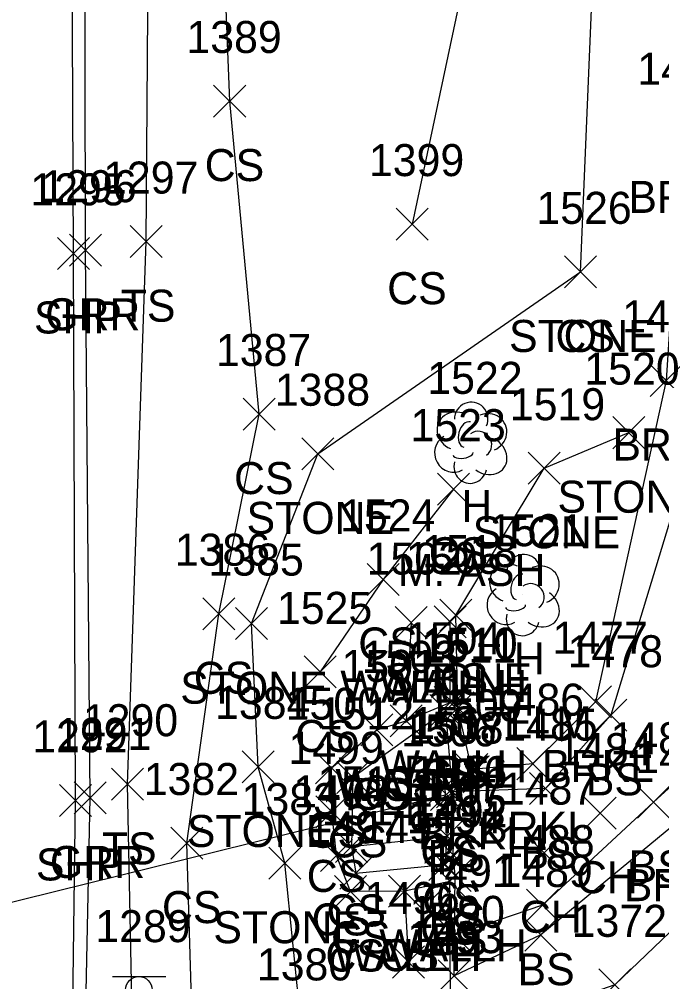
# Model space of a CAD drawing. Extents: x 1618262 to 1622220, y 273782 to 283685.
# Drawn here: x 1622080.2 to 1622120.3, y 282698.6 to 282758.7 of the extents above; entities that cross this region are included whole.
import ezdxf

# ---------------------------------------------------------------- set-up
doc = ezdxf.new("R2010")
doc.units = 0
for name, color, linetype in [('D_A', 7, 'Continuous'), ('D_I', 7, 'Continuous'), ('D_TIC', 7, 'Continuous'), ('DCP', 7, 'Continuous'), ('DHW', 7, 'Continuous'), ('L_A', 7, 'Continuous'), ('L_C', 7, 'Continuous'), ('L_I', 7, 'Continuous'), ('L_TIC', 7, 'Continuous'), ('LASF', 7, 'Continuous'), ('LAWE', 7, 'Continuous'), ('LELB', 7, 'Continuous'), ('LTD', 7, 'Continuous'), ('P_A', 7, 'Continuous'), ('P_I', 7, 'Continuous'), ('P_TIC', 7, 'Continuous'), ('PSP', 7, 'Continuous'), ('R_A', 7, 'Continuous'), ('R_I', 7, 'Continuous'), ('R_TIC', 7, 'Continuous'), ('RGR', 7, 'Continuous'), ('S_I', 7, 'Continuous'), ('SSGN', 7, 'Continuous')]:
    doc.layers.add(name, color=color, linetype=linetype)

msp = doc.modelspace()

# ---------------------------------------------------------------- linework, layer by layer
at = {"layer": 'D_TIC'}
for points in [[(1622106.144, 282720.106), (1622108.144, 282722.106)], [(1622108.144, 282720.106), (1622106.144, 282722.106)], [(1622103.693, 282720.06), (1622105.693, 282722.06)], [(1622105.693, 282720.06), (1622103.693, 282722.06)], [(1622106.143, 282715.082), (1622108.143, 282717.082)], [(1622108.143, 282715.082), (1622106.143, 282717.082)], [(1622103.384, 282713.927), (1622105.384, 282715.927)], [(1622105.384, 282713.927), (1622103.384, 282715.927)], [(1622105.908, 282709.335), (1622107.908, 282711.335)], [(1622107.908, 282709.335), (1622105.908, 282711.335)], [(1622106.12, 282703.906), (1622108.12, 282705.906)], [(1622108.12, 282703.906), (1622106.12, 282705.906)], [(1622103.281, 282703.297), (1622105.281, 282705.297)], [(1622105.281, 282703.297), (1622103.281, 282705.297)], [(1622103.534, 282698.869), (1622105.534, 282700.869)], [(1622105.534, 282698.869), (1622103.534, 282700.869)]]:
    msp.add_lwpolyline(points, dxfattribs=at)
at = {"layer": 'DCP'}
msp.add_lwpolyline([(1622023.295, 282689.629), (1622106.908, 282710.335)], dxfattribs=at)
at = {"layer": 'DHW'}
for points in [[(1622104.693, 282721.06), (1622104.384, 282714.927), (1622107.143, 282716.082), (1622107.144, 282721.106)], [(1622107.156, 282697.422), (1622107.12, 282704.906), (1622104.281, 282704.297), (1622104.534, 282699.869)]]:
    msp.add_lwpolyline(points, dxfattribs=at)
at = {"layer": 'L_TIC'}
for points in [[(1622092.371, 282752.634), (1622094.371, 282754.634)], [(1622094.371, 282752.634), (1622092.371, 282754.634)], [(1622103.765, 282744.946), (1622105.765, 282746.946)], [(1622105.765, 282744.946), (1622103.765, 282746.946)], [(1622087.16, 282743.854), (1622089.16, 282745.854)], [(1622089.16, 282743.854), (1622087.16, 282745.854)], [(1622114.268, 282741.964), (1622116.268, 282743.964)], [(1622116.268, 282741.964), (1622114.268, 282743.964)], [(1622114.268, 282741.964), (1622116.268, 282743.964)], [(1622116.268, 282741.964), (1622114.268, 282743.964)], [(1622119.62, 282735.185), (1622121.62, 282737.185)], [(1622121.62, 282735.185), (1622119.62, 282737.185)], [(1622094.205, 282733.089), (1622096.205, 282735.089)], [(1622096.205, 282733.089), (1622094.205, 282735.089)], [(1622117.294, 282731.925), (1622119.294, 282733.925)], [(1622119.294, 282731.925), (1622117.294, 282733.925)], [(1622097.882, 282730.605), (1622099.882, 282732.605)], [(1622099.882, 282730.605), (1622097.882, 282732.605)], [(1622111.999, 282729.702), (1622113.999, 282731.702)], [(1622113.999, 282729.702), (1622111.999, 282731.702)], [(1622106.354, 282728.393), (1622108.354, 282730.393)], [(1622108.354, 282728.393), (1622106.354, 282730.393)], [(1622101.958, 282722.759), (1622103.958, 282724.759)], [(1622103.958, 282722.759), (1622101.958, 282724.759)], [(1622091.692, 282720.617), (1622093.692, 282722.617)], [(1622093.692, 282720.617), (1622091.692, 282722.617)], [(1622106.5, 282720.524), (1622108.5, 282722.524)], [(1622108.5, 282720.524), (1622106.5, 282722.524)], [(1622106.5, 282720.524), (1622108.5, 282722.524)], [(1622108.5, 282720.524), (1622106.5, 282722.524)], [(1622093.742, 282719.999), (1622095.742, 282721.999)], [(1622095.742, 282719.999), (1622093.742, 282721.999)], [(1622098.016, 282716.984), (1622100.016, 282718.984)], [(1622100.016, 282716.984), (1622098.016, 282718.984)], [(1622106.608, 282714.746), (1622108.608, 282716.746)], [(1622108.608, 282714.746), (1622106.608, 282716.746)], [(1622106.608, 282714.746), (1622108.608, 282716.746)], [(1622108.608, 282714.746), (1622106.608, 282716.746)], [(1622115.219, 282715.114), (1622117.219, 282717.114)], [(1622117.219, 282715.114), (1622115.219, 282717.114)], [(1622105.865, 282714.564), (1622107.865, 282716.564)], [(1622107.865, 282714.564), (1622105.865, 282716.564)], [(1622105.865, 282714.564), (1622107.865, 282716.564)], [(1622107.865, 282714.564), (1622105.865, 282716.564)], [(1622116.166, 282714.275), (1622118.166, 282716.275)], [(1622118.166, 282714.275), (1622116.166, 282716.275)], [(1622103.384, 282713.927), (1622105.384, 282715.927)], [(1622105.384, 282713.927), (1622103.384, 282715.927)], [(1622101.555, 282713.362), (1622103.555, 282715.362)], [(1622103.555, 282713.362), (1622101.555, 282715.362)], [(1622111.294, 282711.254), (1622113.294, 282713.254)], [(1622113.294, 282711.254), (1622111.294, 282713.254)], [(1622094.152, 282711.05), (1622096.152, 282713.05)], [(1622096.152, 282711.05), (1622094.152, 282713.05)], [(1622098.727, 282711.001), (1622100.727, 282713.001)], [(1622100.727, 282711.001), (1622098.727, 282713.001)], [(1622107.48, 282710.9), (1622109.48, 282712.9)], [(1622109.48, 282710.9), (1622107.48, 282712.9)], [(1622085.983, 282709.968), (1622087.983, 282711.968)], [(1622087.983, 282709.968), (1622085.983, 282711.968)], [(1622100.055, 282710.4), (1622102.055, 282712.4)], [(1622102.055, 282710.4), (1622100.055, 282712.4)], [(1622100.055, 282710.4), (1622102.055, 282712.4)], [(1622102.055, 282710.4), (1622100.055, 282712.4)], [(1622105.831, 282709.797), (1622107.831, 282711.797)], [(1622107.831, 282709.797), (1622105.831, 282711.797)], [(1622105.831, 282709.797), (1622107.831, 282711.797)], [(1622107.831, 282709.797), (1622105.831, 282711.797)], [(1622106.286, 282709.498), (1622108.286, 282711.498)], [(1622108.286, 282709.498), (1622106.286, 282711.498)], [(1622106.286, 282709.498), (1622108.286, 282711.498)], [(1622108.286, 282709.498), (1622106.286, 282711.498)], [(1622112.087, 282709.695), (1622114.087, 282711.695)], [(1622114.087, 282709.695), (1622112.087, 282711.695)], [(1622118.838, 282708.844), (1622120.838, 282710.844)], [(1622120.838, 282708.844), (1622118.838, 282710.844)], [(1622098.741, 282708.244), (1622100.741, 282710.244)], [(1622100.741, 282708.244), (1622098.741, 282710.244)], [(1622115.507, 282708.161), (1622117.507, 282710.161)], [(1622117.507, 282708.161), (1622115.507, 282710.161)], [(1622089.701, 282706.297), (1622091.701, 282708.297)], [(1622091.701, 282706.297), (1622089.701, 282708.297)], [(1622105.945, 282706.718), (1622107.945, 282708.718)], [(1622107.945, 282706.718), (1622105.945, 282708.718)], [(1622105.945, 282706.718), (1622107.945, 282708.718)], [(1622107.945, 282706.718), (1622105.945, 282708.718)], [(1622099.976, 282706.09), (1622101.976, 282708.09)], [(1622101.976, 282706.09), (1622099.976, 282708.09)], [(1622099.976, 282706.09), (1622101.976, 282708.09)], [(1622101.976, 282706.09), (1622099.976, 282708.09)], [(1622111.997, 282705.696), (1622113.997, 282707.696)], [(1622113.997, 282705.696), (1622111.997, 282707.696)], [(1622099.039, 282705.528), (1622101.039, 282707.528)], [(1622101.039, 282705.528), (1622099.039, 282707.528)], [(1622106.333, 282705.567), (1622108.333, 282707.567)], [(1622108.333, 282705.567), (1622106.333, 282707.567)], [(1622095.809, 282705.041), (1622097.809, 282707.041)], [(1622097.809, 282705.041), (1622095.809, 282707.041)], [(1622105.815, 282704.955), (1622107.815, 282706.955)], [(1622107.815, 282704.955), (1622105.815, 282706.955)], [(1622100.254, 282704.409), (1622102.254, 282706.409)], [(1622102.254, 282704.409), (1622100.254, 282706.409)], [(1622106.455, 282704.275), (1622108.455, 282706.275)], [(1622108.455, 282704.275), (1622106.455, 282706.275)], [(1622099.907, 282703.275), (1622101.907, 282705.275)], [(1622101.907, 282703.275), (1622099.907, 282705.275)], [(1622103.281, 282703.297), (1622105.281, 282705.297)], [(1622105.281, 282703.297), (1622103.281, 282705.297)], [(1622111.9, 282702.419), (1622113.9, 282704.419)], [(1622113.9, 282702.419), (1622111.9, 282704.419)], [(1622106.406, 282700.551), (1622108.406, 282702.551)], [(1622108.406, 282700.551), (1622106.406, 282702.551)], [(1622106.406, 282700.551), (1622108.406, 282702.551)], [(1622108.406, 282700.551), (1622106.406, 282702.551)], [(1622111.791, 282700.556), (1622113.791, 282702.556)], [(1622113.791, 282700.556), (1622111.791, 282702.556)], [(1622106.385, 282698), (1622108.385, 282700)], [(1622108.385, 282698), (1622106.385, 282700)], [(1622106.385, 282698), (1622108.385, 282700)], [(1622108.385, 282698), (1622106.385, 282700)], [(1622116.42, 282697.441), (1622118.42, 282699.441)], [(1622118.42, 282697.441), (1622116.42, 282699.441)]]:
    msp.add_lwpolyline(points, dxfattribs=at)
at = {"layer": 'LASF'}
for points in [[(1622145.163, 282735.978), (1622143.678, 282720.136), (1622134.988, 282707.013), (1622124.116, 282693.112), (1622102.742, 282693.292), (1622097.849, 282695.719), (1622096.809, 282706.041), (1622095.152, 282712.05), (1622094.742, 282720.999), (1622098.882, 282731.605), (1622115.268, 282742.964)], [(1622107.5, 282721.524), (1622112.999, 282730.702), (1622118.294, 282732.925)]]:
    msp.add_lwpolyline(points, dxfattribs=at)
at = {"layer": 'LAWE'}
for points in [[(1622141.322, 282807.197), (1622130.736, 282774.943), (1622121.615, 282751.647), (1622120.62, 282736.185), (1622116.219, 282716.114), (1622112.294, 282712.254), (1622108.48, 282711.9), (1622107.608, 282715.746)], [(1622154.178, 282798.359), (1622145.032, 282776.682), (1622137.038, 282744.352), (1622134.906, 282727.302), (1622131.147, 282718.739), (1622121.386, 282708.668), (1622112.791, 282701.556), (1622107.385, 282699)]]:
    msp.add_lwpolyline(points, dxfattribs=at)
at = {"layer": 'LELB'}
for points in [[(1622121.158, 282596.521), (1622112.16, 282596.839), (1622102.984, 282598.765), (1622094.202, 282601.848), (1622088.687, 282605.568), (1622085.727, 282618.96), (1622084.898, 282649.699), (1622087.596, 282681.102), (1622086.983, 282710.968), (1622088.16, 282744.854), (1622088.43, 282782.064), (1622089.473, 282801.31), (1622094.579, 282809.136), (1622103.227, 282816.892), (1622109.052, 282823.895), (1622118.477, 282854.453), (1622116.353, 282881.374), (1622111.854, 282914.537), (1622109.182, 282938.553)], [(1622091.189, 282690.575), (1622090.701, 282707.297), (1622092.692, 282721.617), (1622095.205, 282734.089), (1622093.371, 282753.634), (1622092.46, 282776.611), (1622095.588, 282800.789), (1622106.617, 282809.831), (1622119.286, 282825.775), (1622124.751, 282845.144)], [(1622120.134, 282809.332), (1622114.525, 282791.456), (1622109.071, 282766.256), (1622104.765, 282745.946)], [(1622143.151, 282805.581), (1622132.746, 282774.795), (1622123.45, 282751.287), (1622123, 282734.461), (1622117.166, 282715.275), (1622113.087, 282710.695), (1622107.286, 282710.498)], [(1622152.576, 282798.165), (1622142.264, 282776.026), (1622135.441, 282744.305), (1622133.432, 282728.566), (1622130.817, 282719.866), (1622119.838, 282709.844), (1622112.9, 282703.419), (1622107.406, 282701.551), (1622107.455, 282705.275), (1622107.333, 282706.567), (1622107.286, 282710.498), (1622106.865, 282715.564)], [(1622157.901, 282795.316), (1622151.518, 282778.21), (1622146.295, 282745.577), (1622145.163, 282735.978), (1622131.784, 282716.638), (1622123.793, 282704.55), (1622117.42, 282698.441), (1622102.742, 282693.292)], [(1622115.268, 282742.964), (1622116.153, 282763.848), (1622121.586, 282776.181), (1622129.44, 282789.593)], [(1622107.354, 282729.393), (1622102.958, 282723.759), (1622099.016, 282717.984)], [(1622107.608, 282715.746), (1622107.5, 282721.524)], [(1622106.865, 282715.564), (1622101.055, 282711.4), (1622100.976, 282707.09), (1622101.254, 282705.409), (1622106.815, 282705.955), (1622106.945, 282707.718), (1622106.831, 282710.797)], [(1622104.281, 282704.297), (1622100.907, 282704.275), (1622100.039, 282706.528), (1622099.741, 282709.244), (1622099.727, 282712.001), (1622102.555, 282714.362), (1622104.384, 282714.927)], [(1622101.055, 282711.4), (1622106.831, 282710.797)], [(1622100.976, 282707.09), (1622106.945, 282707.718)], [(1622107.385, 282699), (1622107.406, 282701.551)]]:
    msp.add_lwpolyline(points, dxfattribs=at)
at = {"layer": 'LTD'}
for p, q in [((1622108.403, 282732.347), (1622108.403, 282732.347)), ((1622108.403, 282732.347), (1622108.403, 282732.347)), ((1622111.677, 282722.834), (1622111.677, 282722.834)), ((1622111.677, 282722.834), (1622111.677, 282722.834))]:
    msp.add_line(p, q, dxfattribs=at)
for centre in [(1622108.45, 282733.781), (1622111.724, 282724.268)]:
    msp.add_arc(centre, 1.047, 335.52715, 180.95627, dxfattribs=at)
for centre, major_axis, ratio, start_param, end_param in [((1622107.611, 282733.013), (1.21, -0.512), 0.895232, 1.570796, 4.712389), ((1622109.444, 282732.93), (-1.141, -0.483), 0.949671, 1.570796, 4.712389), ((1622108.194, 282732.805), (-0.208, -0.792), 0.645439, 3.141593, 6.283185), ((1622108.903, 282732.18), (-0.5, 0.667), 0.989748, 3.141593, 6.283185), ((1622107.32, 282731.638), (0.584, -1.042), 0.959034, 3.141593, 6.283185), ((1622109.403, 282731.514), (-1.09, 0.792), 0.841452, 1.570796, 4.712389), ((1622107.945, 282731.597), (-0.625, -0.083), 0.423636, 0, 3.141593), ((1622108.403, 282730.847), (0.265, 1.061), 0.942809, 1.570796, 4.712389), ((1622110.885, 282723.5), (1.21, -0.512), 0.895232, 1.570796, 4.712389), ((1622112.718, 282723.417), (-1.141, -0.483), 0.949671, 1.570796, 4.712389), ((1622111.468, 282723.292), (-0.208, -0.792), 0.645439, 3.141593, 6.283185), ((1622112.177, 282722.667), (-0.5, 0.667), 0.989748, 3.141593, 6.283185), ((1622110.594, 282722.125), (0.584, -1.042), 0.959034, 3.141593, 6.283185), ((1622112.677, 282722.001), (-1.09, 0.792), 0.841452, 1.570796, 4.712389), ((1622111.219, 282722.084), (-0.625, -0.083), 0.423636, 0, 3.141593), ((1622111.677, 282721.334), (0.265, 1.061), 0.942809, 1.570796, 4.712389)]:
    msp.add_ellipse(centre, major_axis=major_axis, ratio=ratio, start_param=start_param, end_param=end_param, dxfattribs=at)
at = {"layer": 'P_TIC'}
for points in [[(1622082.621, 282743.119), (1622084.621, 282745.119)], [(1622084.621, 282743.119), (1622082.621, 282745.119)], [(1622082.739, 282708.962), (1622084.739, 282710.962)], [(1622084.739, 282708.962), (1622082.739, 282710.962)]]:
    msp.add_lwpolyline(points, dxfattribs=at)
at = {"layer": 'PSP'}
msp.add_lwpolyline([(1622063.899, 282356.417), (1622068.955, 282404.452), (1622072.02, 282437.728), (1622074.665, 282475.613), (1622076.635, 282501.43), (1622078.271, 282531.064), (1622079.381, 282546.297), (1622079.58, 282558.785), (1622081.734, 282610.733), (1622082.589, 282649.97), (1622083.395, 282682.719), (1622083.739, 282709.962), (1622083.621, 282744.119), (1622083.448, 282781.355), (1622083.165, 282811.548), (1622082.701, 282831.314), (1622081.46, 282858.351), (1622080.359, 282881.435), (1622078.26, 282910.946), (1622077.134, 282929.735), (1622076.71, 282935.514)], dxfattribs=at)
at = {"layer": 'R_TIC'}
for points in [[(1622083.362, 282743.316), (1622085.362, 282745.316)], [(1622085.362, 282743.316), (1622083.362, 282745.316)], [(1622083.658, 282709.116), (1622085.658, 282711.116)], [(1622085.658, 282709.116), (1622083.658, 282711.116)]]:
    msp.add_lwpolyline(points, dxfattribs=at)
at = {"layer": 'RGR'}
msp.add_lwpolyline([(1622085.58, 282605.247), (1622083.68, 282611.3), (1622082.779, 282619.397), (1622083.481, 282650.056), (1622084.103, 282682.868), (1622084.658, 282710.116), (1622084.362, 282744.316), (1622084.303, 282781.106), (1622084.959, 282794.061), (1622087.053, 282807.794)], dxfattribs=at)
at = {"layer": 'SSGN'}
msp.add_line((1622086.056, 282698.962), (1622089.39, 282698.962), dxfattribs=at)
msp.add_circle((1622087.703, 282698.128), 0.833, dxfattribs=at)

# ---------------------------------------------------------------- texts
at = {"layer": 'D_A'}
for s, p in [('WALLH', (1622100.283, 282716.06)), ('WALLH', (1622102.735, 282716.106)), ('WALLH', (1622102.734, 282711.082)), ('WALLH', (1622099.975, 282709.927)), ('P', (1622106.286, 282705.335)), ('WALLH', (1622102.711, 282699.906)), ('WALLH', (1622099.871, 282699.297))]:
    msp.add_text(s, height=2, dxfattribs=at).set_placement(p)
at = {"layer": 'D_I'}
for s, p in [('1502', (1622101.921, 282724.06)), ('1505', (1622104.373, 282724.106)), ('1504', (1622104.372, 282719.082)), ('1503', (1622101.612, 282717.927)), ('1506', (1622104.082, 282713.335)), ('1494', (1622104.427, 282707.906)), ('1495', (1622101.588, 282707.297)), ('1496', (1622101.786, 282702.869)), ('1493', (1622104.463, 282700.422))]:
    msp.add_text(s, height=2, dxfattribs=at).set_placement(p)
at = {"layer": 'L_A'}
for s, p in [('CS', (1622091.812, 282748.634)), ('BRKL', (1622118.261, 282746.647)), ('CS', (1622103.206, 282740.946)), ('TS', (1622086.57, 282739.854)), ('STONE', (1622110.812, 282737.964)), ('CS', (1622113.709, 282737.964)), ('BRKL', (1622117.266, 282731.185)), ('CS', (1622093.646, 282729.089)), ('STONE', (1622113.837, 282727.925)), ('H', (1622107.836, 282727.347)), ('STONE', (1622094.425, 282726.605)), ('STONE', (1622108.542, 282725.702)), ('CS', (1622105.795, 282724.393)), ('CS', (1622101.399, 282718.759)), ('H', (1622111.11, 282717.834)), ('CS', (1622091.133, 282716.617)), ('STONE', (1622103.044, 282716.524)), ('BS', (1622105.941, 282716.524)), ('STONE', (1622090.285, 282715.999)), ('CS', (1622097.457, 282712.984)), ('BRKL', (1622112.865, 282711.114)), ('BRKL', (1622104.253, 282710.746)), ('CS', (1622105.306, 282710.564)), ('BS', (1622105.306, 282710.564)), ('BS', (1622106.049, 282710.746)), ('CS', (1622102.825, 282709.927)), ('BS', (1622115.607, 282710.275)), ('CS', (1622100.996, 282709.362)), ('STONE', (1622090.695, 282707.05)), ('CS', (1622098.168, 282707.001)), ('BRKL', (1622105.126, 282706.9)), ('BRKL', (1622108.94, 282707.254)), ('CS', (1622099.496, 282706.4)), ('CS', (1622099.496, 282706.4)), ('TS', (1622085.393, 282705.968)), ('CS', (1622105.272, 282705.797)), ('CS', (1622105.272, 282705.797)), ('BS', (1622111.528, 282705.695)), ('BS', (1622105.727, 282705.498)), ('BS', (1622105.727, 282705.498)), ('BS', (1622118.279, 282704.844)), ('CS', (1622098.182, 282704.244)), ('CH', (1622114.995, 282704.161)), ('BRKR', (1622117.976, 282703.668)), ('CS', (1622105.386, 282702.718)), ('CS', (1622105.386, 282702.718)), ('CS', (1622089.142, 282702.297)), ('CS', (1622099.417, 282702.09)), ('CS', (1622099.417, 282702.09)), ('CS', (1622098.48, 282701.528)), ('BS', (1622105.774, 282701.567)), ('CH', (1622111.485, 282701.696)), ('STONE', (1622092.353, 282701.041)), ('CS', (1622105.256, 282700.955)), ('CS', (1622099.695, 282700.409)), ('BS', (1622105.896, 282700.275)), ('CS', (1622099.348, 282699.275)), ('CS', (1622102.722, 282699.297)), ('BS', (1622111.341, 282698.419))]:
    msp.add_text(s, height=2, dxfattribs=at).set_placement(p)
at = {"layer": 'L_C'}
for s, p in [('M. ASH', (1622103.868, 282723.347)), ('S. ELM', (1622107.22, 282713.834))]:
    msp.add_text(s, height=2, dxfattribs=at).set_placement(p)
at = {"layer": 'L_I'}
for s, p in [('1389', (1622090.67, 282756.634)), ('1466', (1622118.82, 282754.647)), ('1399', (1622102.065, 282748.946)), ('1297', (1622085.468, 282747.854)), ('1526', (1622112.521, 282745.964)), ('1526', (1622112.521, 282745.964)), ('1476', (1622117.872, 282739.185)), ('1387', (1622092.512, 282737.089)), ('1520', (1622115.514, 282735.925)), ('1522', (1622105.71, 282735.347)), ('1388', (1622096.189, 282734.605)), ('1519', (1622110.865, 282733.702)), ('1523', (1622104.661, 282732.393)), ('1524', (1622100.265, 282726.759)), ('1521', (1622109.551, 282725.834)), ('1386', (1622089.944, 282724.617)), ('1518', (1622105.375, 282724.524)), ('1518', (1622105.375, 282724.524)), ('1385', (1622092.049, 282723.999)), ('1525', (1622096.323, 282720.984)), ('1477', (1622113.526, 282719.114)), ('1511', (1622105.306, 282718.564)), ('1511', (1622105.306, 282718.564)), ('1510', (1622105.396, 282718.746)), ('1510', (1622105.396, 282718.746)), ('1478', (1622114.474, 282718.275)), ('1503', (1622101.612, 282717.927)), ('1501', (1622100.351, 282717.362)), ('1486', (1622109.547, 282715.254)), ('1384', (1622092.459, 282715.05)), ('1500', (1622096.869, 282715.001)), ('1509', (1622105.701, 282714.9)), ('1512', (1622098.929, 282714.4)), ('1512', (1622098.929, 282714.4)), ('1290', (1622084.204, 282713.968)), ('1508', (1622104.514, 282713.498)), ('1508', (1622104.514, 282713.498)), ('1517', (1622104.705, 282713.797)), ('1517', (1622104.705, 282713.797)), ('1485', (1622110.394, 282713.695)), ('1483', (1622117.145, 282712.844)), ('1499', (1622097.04, 282712.244)), ('1484', (1622113.814, 282712.161)), ('1482', (1622118.693, 282711.668)), ('1516', (1622104.764, 282710.718)), ('1516', (1622104.764, 282710.718)), ('1382', (1622088.008, 282710.297)), ('1513', (1622098.851, 282710.09)), ('1513', (1622098.851, 282710.09)), ('1498', (1622097.346, 282709.528)), ('1507', (1622104.562, 282709.567)), ('1487', (1622110.304, 282709.696)), ('1383', (1622094.117, 282709.041)), ('1515', (1622104.69, 282708.955)), ('1514', (1622099.128, 282708.409)), ('1492', (1622104.762, 282708.275)), ('1497', (1622098.214, 282707.275)), ('1495', (1622101.588, 282707.297)), ('1488', (1622110.208, 282706.419)), ('1491', (1622105.28, 282704.551)), ('1491', (1622105.28, 282704.551)), ('1489', (1622110.09, 282704.556)), ('1490', (1622104.606, 282702)), ('1490', (1622104.606, 282702)), ('1372', (1622114.727, 282701.441)), ('1380', (1622095.07, 282698.719)), ('1380', (1622095.07, 282698.719))]:
    msp.add_text(s, height=2, dxfattribs=at).set_placement(p)
at = {"layer": 'P_A'}
for p in [(1622081.156, 282739.119), (1622081.274, 282704.962)]:
    msp.add_text('SHP', height=2, dxfattribs=at).set_placement(p)
at = {"layer": 'P_I'}
for s, p in [('1295', (1622080.928, 282747.119)), ('1292', (1622081.046, 282712.962))]:
    msp.add_text(s, height=2, dxfattribs=at).set_placement(p)
at = {"layer": 'R_A'}
for p in [(1622081.85, 282739.316), (1622082.146, 282705.116)]:
    msp.add_text('GRR', height=2, dxfattribs=at).set_placement(p)
at = {"layer": 'R_I'}
for s, p in [('1296', (1622081.614, 282747.316)), ('1291', (1622082.533, 282713.116))]:
    msp.add_text(s, height=2, dxfattribs=at).set_placement(p)
at = {"layer": 'S_I'}
msp.add_text('1289', height=2, dxfattribs=at).set_placement((1622084.983, 282701.108))

doc.saveas('drawing.dxf')
